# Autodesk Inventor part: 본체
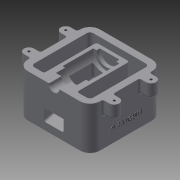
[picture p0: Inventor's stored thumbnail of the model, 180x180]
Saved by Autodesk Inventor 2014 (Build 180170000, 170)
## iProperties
Created: 2018-01
Part Number: 본체
Material: Generic
Document SubType Name: Modeling
Designer: Administrator
Density: 1 g/cm^3
Appearance: Default
Author: Administrator
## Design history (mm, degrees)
sketch "Sketch1"
  geometry: L1 (-40, 55)-(40, 55); L2 (55, 40)-(55, -40); L3 (40, -55)-(-40, -55); L4 (-55, -40)-(-55, 40); L5 (-55, 55)-(55, -55); L6 (55, 55)-(-55, -55); L7 (40, 45)-(-40, 45); L8 (-40, -45)-(40, -45); L9 (45, -40)-(45, 40); L10 (17.238, 25)-(-45, 25); L11 (17.238, 25)-(35, 25); L12 (35, 25)-(35, -25); L13 (35, -25)-(-45, -25); L14 (-45, 40)-(-45, 25); L15 (-45, -25)-(-45, -40); A1 r 15 centre (-40, 40) between (-40, 55) and (-55, 40); A2 r 15 centre (-40, -40) between (-55, -40) and (-40, -55); A3 r 15 centre (40, -40) between (40, -55) and (55, -40); A4 r 15 centre (40, 40) between (55, 40) and (40, 55); A5 r 5 centre (-40, 40) between (-40, 45) and (-45, 40); A6 r 5 centre (-40, -40) between (-45, -40) and (-40, -45); A7 r 5 centre (40, -40) between (40, -45) and (45, -40); A8 r 5 centre (40, 40) between (45, 40) and (40, 45); 1 further point
  constraints: 30 end point, 16 point on circle, 8 centre point, 8 point on line, 8 tangent, 6 perpendicular, 5 parallel, 3 equal radius, 2 midpoint, 1 horizontal, 5 other
  dimensions: "d0" = 110 distance between parallel lines of L2 L4; "d1" = 110 distance between parallel lines of L3 L1; "d2" = 15 radius of A1; "d3" = 10 distance between parallel lines of L2 L9; "d8" = 25 distance from line of L10 point (0, 0); "d9" = 10 distance between parallel lines of L4 L15; "d10" = 45 distance from line of point (0, 0) L15 (derived); "d11" = 25 distance from line of point (0, 0) L13; "d12" = 90 distance between parallel lines of L7 L8; "d13" = 10 distance between parallel lines of L9 L12
extrude "Extrusion1" new body sketch "Sketch1" distance "d14" = 65; taper "d15" = 0 deg
fillet "Fillet1" dims "d25" = 3
sketch "Sketch7"
  geometry: L1 (-55, 0)-(-55, 65) reference; L2 (-55, 65)-(-45, 65) reference; L3 (-45, 65)-(-45, 0) reference; L4 (-45, 0)-(-55, 0) reference; L5 (55, 65)-(55, 0) reference; L6 (55, 0)-(-35, 0) reference; L7 (-35, 0)-(-35, 65) reference; L8 (-35, 65)-(55, 65) reference; L9 (55, 65)-(-35, 65); L10 (55, 65)-(55, 72.5); L11 (55, 72.5)-(36, 72.5); L12 (36, 72.5)-(36, 80); L13 (35, 81)-(22, 81); L14 (22, 81)-(22, 84); L15 (21, 85)-(-24, 85); L16 (-25, 84)-(-25, 80); L17 (-25, 80)-(-29, 80); L18 (-30, 79)-(-30, 65); A1 r 1 centre (35, 80) between (36, 80) and (35, 81); A2 r 1 centre (21, 84) between (22, 84) and (21, 85); A3 r 1 centre (-24, 84) between (-24, 85) and (-25, 84); A4 r 1 centre (-29, 79) between (-29, 80) and (-30, 79); 5 further points
  constraints: 20 end point, 10 point on line, 9 perpendicular, 8 point on circle, 8 tangent, 4 centre point, 3 equal radius, 1 collinear
  dimensions: "d40" = 15 diameter of L10.end L8; "d41" = 19 distance from line of L11.end L10; "d42" = 32 diameter of point (36, 81) L8; "d43" = 14 distance from line of L13.end L12; "d44" = 40 diameter of L15 L8; "d45" = 47 distance from line of point (-25, 85) L14; "d46" = 5 distance from line of point (-30, 80) L16; "d47" = 30 diameter of L17 L9; "d76" = 1 radius of A1
revolve "Revolution1" sketch "Sketch7" stored, may be unused: angle "d48" = 90 deg
sketch "Sketch11"
  geometry: L1 (-30, 65)-(-30, 51) reference; L2 (-29, 50)-(-25, 50) reference; L3 (-25, 50)-(-25, 46) reference; L4 (22, 46)-(22, 49) reference; L5 (22, 49)-(35, 49) reference; L6 (36, 50)-(36, 57.5) reference; L7 (36, 57.5)-(55, 57.5) reference; L8 (55, 57.5)-(55, 0) reference; L9 (55, 0)-(-35, 0) reference; L10 (-35, 0)-(-35, 65) reference; L11 (-35, 65)-(-30, 65) reference; L12 (-55, 65)-(-45, 65) reference; L13 (-45, 65)-(-45, 0) reference; L14 (-45, 0)-(-55, 0) reference; L15 (-55, 0)-(-55, 65) reference; L16 (-35, 30)-(45, 8.564); L17 (45, 0)-(45, 8.564); L18 (-35, 0)-(45, 0); L19 (-35, 30)-(-35, 0); L20 (-24, 45)-(21, 45) reference; A1 r 1 centre (-29, 51) between (-30, 51) and (-29, 50) reference; A2 r 1 centre (-24, 46) between (-25, 46) and (-24, 45) reference; A3 r 1 centre (21, 46) between (21, 45) and (22, 46) reference; A4 r 1 centre (35, 50) between (35, 49) and (36, 50) reference; 1 further point
  constraints: 8 end point, 3 point on line, 2 collinear
  dimensions: "d61" = 30 distance from line of L16.start L14; "d63" = 105 deg angle of L10 L16; "d64" = 8.56406 distance from line of L16.end L9; "d65" = 80 distance from line of L17.start L10
extrude "Extrusion3" cut sketch "Sketch11" stored distance "d66" = 55; taper "d67" = 0 deg
sketch "Sketch12"
  geometry: L1 (-35, 30)-(42, 9.368) reference; L2 (-17.776, 30.561)-(55, 11.061); L3 (55, 0)-(55, 65) reference; L4 (-24, 45)-(21, 45) reference; L5 (19.224, 38.647)-(55, 29.061); L6 (17, 45)-(17, 41.545); L7 (-20, 45)-(-20, 33.459); L8 (55, 29.061)-(55, 11.061); L9 (-20, 45)-(-20, 62.933); L10 (-20, 62.933)-(17, 62.933); L11 (17, 62.933)-(17, 45); A1 r 3 centre (20, 41.545) between (17, 41.545) and (19.224, 38.647); A2 r 3 centre (-17, 33.459) between (-20, 33.459) and (-17.776, 30.561); 6 further points; 2 other entities
  constraints: 16 end point, 5 parallel, 4 point on circle, 4 point on line, 4 tangent, 2 centre point, 2 perpendicular, 1 equal radius, 1 midpoint, 2 other
  dimensions: "d68" = 5 distance between parallel lines of L2 L1; "d70" = 18 distance of L5.end L2.end; "d71" = 18.5 distance of L7.start point (-1.5, 45); "d72" = 18.5 distance of point (-1.5, 45) L6.start; "d73" = 3 radius of A1; "d78" = 17.93347 distance between parallel lines of L10 L4
extrude "Extrusion5" cut sketch "Sketch12" stored distance "d79" = 30; taper "d80" = 0 deg
fillet "Fillet2" dims "d81" = 3
chamfer "Chamfer1" distance "d82" = 1; stored, may be unused: second distance "d83" = 2, angle "d84" = 45 deg
sketch "Sketch13"
  geometry: A1 r 10 centre (-28, -65) between (-38, -65) and (-18, -65) reference; A2 r 10 centre (28, -65) between (18, -65) and (38, -65) reference; A3 r 10 centre (28, 65) between (38, 65) and (18, 65) reference; A4 r 10 centre (-28, 65) between (-18, 65) and (-38, 65) reference; 5 further points
  constraints: 4 coincident
hole "Hole1" sketch "Sketch13" at (-28, 65), (28, 65), (28, -65), (-28, -65) diameter "d85" = 3.459; stored, may be unused: countersink angle "d89" = 90 deg, drill point angle "d91" = 118 deg; dims "d86" = 9, "d87" = 4, "d88" = 2, "d90" = 11
fillet "Fillet24" dims "d113" = 3
fillet "Fillet25" dims "d114" = 3
sketch "Sketch14"
  geometry: L1 (-40, -55)-(40, -55) reference; L2 (55, -40)-(55, 40) reference; L3 (40, 55)-(-40, 55) reference; L4 (-55, 40)-(-55, 8.5) reference; L5 (-35.5, 65)-(-35.5, 55); L6 (-20.5, 65)-(-20.5, 55); L7 (-35.5, 55)-(-20.5, 55); L8 (-55, 0)-(55, 0); L9 (0, 55)-(0, -55); L10 (-40, 55)-(40, 55); L11 (35.5, 55)-(20.5, 55); L12 (35.5, 65)-(35.5, 55); L13 (20.5, 65)-(20.5, 55); L14 (45, -40)-(45, 40); L15 (0, -55)-(0, 55); L16 (-40, -45)-(40, -45); L17 (-45, -28)-(-45, -40); L18 (55, 40)-(55, -40); L19 (-40, -55)-(40, -55); L20 (40, -55)-(-40, -55); L21 (-20.5, -65)-(-20.5, -55); L22 (-35.5, -55)-(-20.5, -55); L23 (-55, -40)-(-55, -8.5); L24 (-35.5, -65)-(-35.5, -55); L25 (20.5, -65)-(20.5, -55); L26 (35.5, -55)-(20.5, -55); L27 (35.5, -65)-(35.5, -55); A1 r 5 centre (-40, 40) between (-40, 45) and (-45, 40) reference; A2 r 5 centre (40, 40) between (45, 40) and (40, 45) reference; A3 r 15 centre (40, 40) between (55, 40) and (40, 55) reference; A4 r 15 centre (-40, 40) between (-40, 55) and (-55, 40) reference; A5 r 7.5 centre (-28, 65) between (-20.5, 65) and (-35.5, 65); A6 r 15 centre (40, 40) between (55, 40) and (40, 55); A7 r 7.5 centre (28, 65) between (35.5, 65) and (20.5, 65); A8 r 5 centre (40, -40) between (40, -45) and (45, -40); A9 r 5 centre (-40, -40) between (-45, -40) and (-40, -45); A10 r 15 centre (-40, -40) between (-55, -40) and (-40, -55); A11 r 7.5 centre (-28, -65) between (-35.5, -65) and (-20.5, -65); A12 r 15 centre (40, -40) between (40, -55) and (55, -40); A13 r 15 centre (40, -40) between (40, -55) and (55, -40); A14 r 7.5 centre (28, -65) between (20.5, -65) and (35.5, -65); 2 further points
  constraints: 46 end point, 33 symmetric about line, 20 point on circle, 10 centre point, 8 point on line, 3 midpoint, 2 parallel, 2 tangent, 1 perpendicular, 9 other
  dimensions: "d116" = 15 diameter of A5; "d117" = 27 distance from line of L4 A5.centre; "d118" = 10 distance from line of A5.centre L3
extrude "Extrusion6" join sketch "Sketch14" distance "d119" = 20; taper "d120" = 0 deg
sketch "Sketch15"
  geometry: A1 r 7.5 centre (-28, -65) between (-35.5, -65) and (-20.5, -65) reference; A2 r 7.5 centre (28, -65) between (20.5, -65) and (35.5, -65) reference; A3 r 7.5 centre (28, 65) between (35.5, 65) and (20.5, 65) reference; A4 r 7.5 centre (-28, 65) between (-20.5, 65) and (-35.5, 65) reference; 5 further points
  constraints: 4 coincident
hole "Hole2" sketch "Sketch15" at (-28, 65), (28, 65), (28, -65), (-28, -65) diameter "d121" = 3.459; stored, may be unused: countersink angle "d125" = 90 deg, drill point angle "d127" = 118 deg; dims "d122" = 9, "d123" = 4, "d124" = 2, "d126" = 11
workplane "Work Plane2"
sketch "Sketch17"
  geometry: L1 (95, 0)-(95, 65) reference; L2 (95, 0)-(80, 0) reference; 2 further points
  constraints: 1 other
  dimensions: "d129" = 55 distance from line of L1 point (40, 20); "d130" = 20 distance from line of L2 point (40, 20)
emboss "Emboss2" sketch "Sketch17" dims "d0" = 110, "d1" = 110, "d2" = 15, "d3" = 10, "d8" = 25, "d9" = 10, "d10" = 45 (derived), "d11" = 25, "d12" = 90, "d13" = 10, "d131" = 0.5, "d132" = 0
fillet "Fillet26" dims "d133" = 3
fillet "Fillet27" dims "d134" = 3
fillet "Fillet28" dims "d135" = 3
fillet "Fillet29" dims "d136" = 3
fillet "Fillet30" dims "d137" = 3
fillet "Fillet31" dims "d138" = 3
fillet "Fillet32" dims "d139" = 3
fillet "Fillet33" dims "d140" = 3
body "Solid1"
node "Project Cut Edges4"
node "Project Cut Edges8"
